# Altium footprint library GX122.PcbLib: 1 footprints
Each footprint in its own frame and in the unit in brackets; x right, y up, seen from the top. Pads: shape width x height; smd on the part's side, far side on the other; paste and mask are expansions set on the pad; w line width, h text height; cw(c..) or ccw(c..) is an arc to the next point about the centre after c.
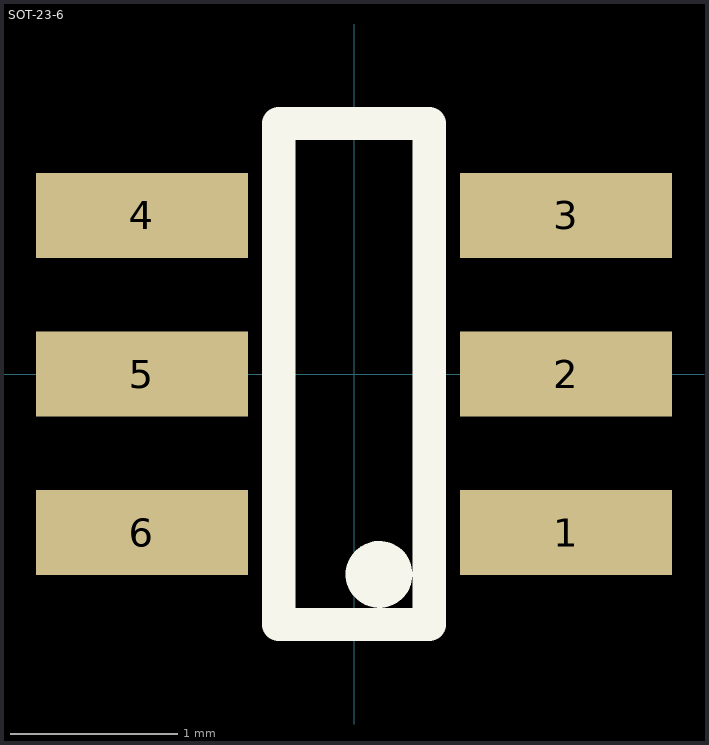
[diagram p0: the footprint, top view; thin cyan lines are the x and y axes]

## SOT-23-6 [mil]
pads (6):
  rect 50x20 smd mask+0.98: 1(50,-37.4) 2(50,0) 3(50,37.4) 4(-50,37.4) 5(-50,0) 6(-50,-37.4)
Top Overlay:
  circle w7.87: c5.91,-47.24 r3.94
  lines w7.87: -17.72,-59.06 17.72,-59.06 17.72,59.06 -17.72,59.06 -17.72,-59.06
3D body "SOT23-6.STEP": height 45.28, standoff -1.16, extent -55.24,-59.05 55.26,59.06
